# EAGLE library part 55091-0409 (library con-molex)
0.635 mm PITCH B TO B CONN. Source: http://www.molex.com/pdm_docs/sd/550911609_sd.pdf
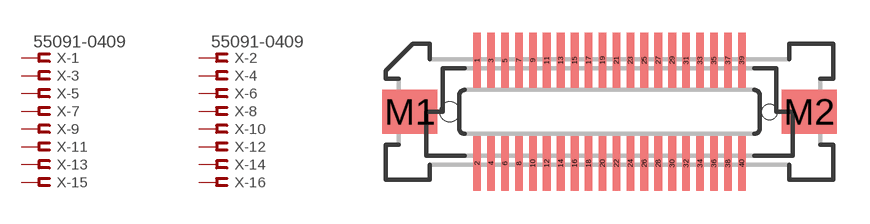
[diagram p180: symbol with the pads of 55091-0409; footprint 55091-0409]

Designator prefix X; gates -1=FV -2=FV -3=F -4=F -5=F -6=F -7=F -8=F -9=F -10=F -11=F -12=F -13=F -14=F -15=F -16=F -17=F -18=F -19=F -20=F -21=F -22=F -23=F -24=F -25=F -26=F -27=F -28=F -29=F -30=F -31=F -32=F -33=F -34=F -35=F -36=F -37=F -38=F -39=F -40=F

## 55091-0409 (OC_FARNELL: unknown; OC_NEWARK: unknown)  [55091-0409]
1  -1:S  pas
2  -2:S  pas
3  -3:S  pas
4  -4:S  pas
5  -5:S  pas
6  -6:S  pas
7  -7:S  pas
8  -8:S  pas
9  -9:S  pas
10  -10:S  pas
11  -11:S  pas
12  -12:S  pas
13  -13:S  pas
14  -14:S  pas
15  -15:S  pas
16  -16:S  pas
17  -17:S  pas
18  -18:S  pas
19  -19:S  pas
20  -20:S  pas
21  -21:S  pas
22  -22:S  pas
23  -23:S  pas
24  -24:S  pas
25  -25:S  pas
26  -26:S  pas
27  -27:S  pas
28  -28:S  pas
29  -29:S  pas
30  -30:S  pas
31  -31:S  pas
32  -32:S  pas
33  -33:S  pas
34  -34:S  pas
35  -35:S  pas
36  -36:S  pas
37  -37:S  pas
38  -38:S  pas
39  -39:S  pas
40  -40:S  pas

## Footprint 55091-0409 (pad centres in mm)
0.635 mm PITCH B TO B CONN. Source: http://www.molex.com/pdm_docs/sd/550911609_sd.pdf
smd 0.35 x 2.5: 1 -6.032,2.35; 2 -6.032,-2.35; 3 -5.397,2.35; 4 -5.397,-2.35; 5 -4.763,2.35; 6 -4.763,-2.35; 7 -4.128,2.35; 8 -4.128,-2.35; 9 -3.493,2.35; 10 -3.493,-2.35; 11 -2.857,2.35; 12 -2.857,-2.35; 13 -2.223,2.35; 14 -2.223,-2.35; 15 -1.587,2.35; 16 -1.587,-2.35; 17 -0.953,2.35; 18 -0.953,-2.35; 19 -0.318,2.35; 20 -0.318,-2.35; 21 0.318,2.35; 22 0.318,-2.35; 23 0.953,2.35; 24 0.953,-2.35; 25 1.587,2.35; 26 1.587,-2.35; 27 2.223,2.35; 28 2.223,-2.35; 29 2.857,2.35; 30 2.857,-2.35; 31 3.493,2.35; 32 3.493,-2.35; 33 4.128,2.35; 34 4.128,-2.35; 35 4.763,2.35; 36 4.763,-2.35; 37 5.397,2.35; 38 5.397,-2.35; 39 6.032,2.35; 40 6.032,-2.35
smd 2.5 x 2: M1 -9.1,0; M2 9.1,0
hole 0.9 at -7.285,0
hole 0.7 at 7.285,0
